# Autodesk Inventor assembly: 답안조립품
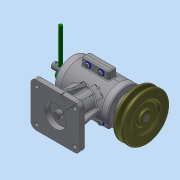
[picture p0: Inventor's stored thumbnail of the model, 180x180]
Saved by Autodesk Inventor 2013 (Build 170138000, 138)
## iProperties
Created: 2015-12
Part Number: 답안조립품
Document SubType Name: Assembly
Designer: Administrator
Mass: 1960.55 g
Surface Area: 1487.03 cm^2
Volume: 472.445 cm^3
Density: 4.14979 g/cm^3
Author: Administrator
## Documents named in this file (19)
- C:\Users\Administrator\Desktop\351208V1035\답안조립품.iam
- C:\Users\Administrator\Desktop\351208V1035\본체.ipt
- C:\Users\Administrator\Desktop\351208V1035\V-벨트풀리.ipt
- C:\Users\Administrator\Desktop\351208V1035\너트 M4.ipt
- C:\Users\Administrator\Desktop\351208V1035\뒤커버.ipt
- C:\Users\Administrator\Desktop\351208V1035\레바.ipt
- C:\Users\Administrator\Desktop\351208V1035\멈춤나사 M3x8.ipt
- C:\Users\Administrator\Desktop\351208V1035\베어링 6201.ipt
- C:\Users\Administrator\Desktop\351208V1035\베어링 6202.ipt
- C:\Users\Administrator\Desktop\351208V1035\본체커버.ipt
- C:\Users\Administrator\Desktop\351208V1035\볼트 M3x0.5x8.ipt
- C:\Users\Administrator\Desktop\351208V1035\볼트 M4 x 16.ipt
- C:\Users\Administrator\Desktop\351208V1035\스프링 - [가변].ipt
- C:\Users\Administrator\Desktop\351208V1035\슬라이드.ipt
- C:\Users\Administrator\Desktop\351208V1035\앞커버.ipt
- C:\Users\Administrator\Desktop\351208V1035\오일실 12 22 7.ipt
- C:\Users\Administrator\Desktop\351208V1035\와셔 ST 4-100.ipt
- C:\Users\Administrator\Desktop\351208V1035\키 4 x 4 x 18.ipt
- C:\Users\Administrator\Desktop\351208V1035\편심축.ipt
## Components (13 placed, 4 different names)
1. V-벨트풀리:1 — 플러쉬:1
2. ISO 4032 M4:1
3. ISO 4762 M4 x 16:1
4. ISO 7091 ST 4 - 100 HV:1
5. ISO 4762 M4 x 16:2
6. ISO 4762 M4 x 16:3
7. ISO 4762 M4 x 16:4
8. ISO 7091 ST 4 - 100 HV:2
9. ISO 7091 ST 4 - 100 HV:3
10. ISO 7091 ST 4 - 100 HV:4
11. ISO 4032 M4:2
12. ISO 4032 M4:3
13. ISO 4032 M4:4
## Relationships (1: Flush 1)
- 플러쉬:1 [Flush]: V-벨트풀리:1
